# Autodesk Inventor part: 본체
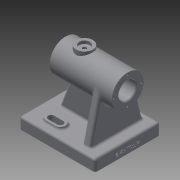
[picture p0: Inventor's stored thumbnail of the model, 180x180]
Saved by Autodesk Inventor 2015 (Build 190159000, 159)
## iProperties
Created: 2022-06
Part Number: 본체
Material: 일반
Document SubType Name: Modeling
Designer: 10401
Density: 1 g/cm^3
Appearance: 기본값
Author: 10401
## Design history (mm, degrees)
sketch "스케치1"
  geometry: C1 r 21 at (0, 0); 1 further point
  constraints: 1 centre point, 1 coincident
  dimensions: "d0" = 42 diameter of C1
extrude "돌출1" new body sketch "스케치1" stored distance "d1" = 82; taper "d2" = 0 deg
sketch "스케치2"
  geometry: L1 (41, 21)-(41, -21) reference; L2 (41, -21)-(-41, -21) reference; L3 (-41, -21)-(-41, 21) reference; L4 (-41, 21)-(41, 21) reference; L5 (41, 0)-(-41, 0); L6 (41, 14.5)-(-21, 14.5); L7 (-21, 14.5)-(-21, 11.5); L8 (-21, 11.5)-(-41, 11.5); 1 further point
  constraints: 8 end point, 2 horizontal, 2 midpoint, 2 point on line, 1 perpendicular
  dimensions: "d3" = 62 distance of L6.start L6.end; "d4" = 29 diameter of L6 L5; "d5" = 23 diameter of L8 L5
revolve "회전1" sketch "스케치2" stored, may be unused: angle "d6" = 90 deg
node "작업 평면2"
sketch "스케치4"
  geometry: L1 (-59, 43)-(41, 43); L2 (41, 43)-(41, -43); L3 (41, -43)-(-59, -43); L4 (-59, -43)-(-59, 43); L5 (41, -21)-(41, 21) reference; L6 (-59, 0)-(41, 0); 1 further point
  constraints: 10 end point, 2 midpoint, 2 parallel, 1 collinear, 1 horizontal, 1 perpendicular, 1 other
  dimensions: "d12" = 86 distance of L1.end L2.end; "d13" = 100 distance of L1.start L1.end
extrude "돌출2" join sketch "스케치4" distance "d14" = 15; taper "d15" = 0 deg
sketch "스케치5"
  geometry: L1 (41, 43)-(-59, 43) reference; L2 (-59, 43)-(-59, -43) reference; L3 (41, -43)-(41, 43) reference; L4 (-44, 5)-(26, 5); L5 (26, 5)-(26, -5); L6 (26, -5)-(-44, -5); L7 (-44, -5)-(-44, 5); L8 (16, 35)-(26, 35); L9 (26, 35)-(26, -35); L10 (26, -35)-(16, -35); L11 (16, -35)-(16, 35); L12 (16, 35)-(26, -35); L13 (26, 35)-(16, -35); L14 (-59, -43)-(41, -43) reference; 4 further points
  constraints: 20 end point, 4 parallel, 3 midpoint, 2 horizontal, 2 perpendicular, 1 collinear, 1 horizontal alignment
  dimensions: "d16" = 10 distance between parallel lines of L9 L11; "d17" = 10 distance of L6.end L4.start; "d18" = 15 distance between parallel lines of L3 L9; "d20" = 15 distance between parallel lines of L2 L7; "d139" = 5 distance from line of L6 point (0, 0); "d140" = 8 distance between parallel lines of L14 L10; "d141" = 8 distance between parallel lines of L1 L8
extrude "돌출3" join sketch "스케치5" distance "d21" = 57; taper "d22" = 0 deg
feature "면 기울기1" dims angle "d23" = 20 deg
node "작업 평면3"
sketch "스케치6"
  geometry: L1 (-15, 86)-(0, 86) reference; L2 (0, 86)-(0, 0) reference; L3 (0, 0)-(-15, 0) reference; L4 (-15, 0)-(-15, 38) reference; L5 (-15, 48)-(-15, 86) reference; L6 (-76.814, 22.559)-(-15, 8); L7 (-76.814, 63.441)-(-15, 78); L8 (-72, 48)-(-61.644, 48) reference; L9 (-61.644, 38)-(-72, 38) reference; L10 (-72, 38)-(-72, 48) reference; L11 (-15, 38)-(-15, 48) reference; L12 (-15, 38)-(-51.604, 38) reference; L13 (-51.604, 48)-(-15, 48) reference; A1 r 11.5 centre (-72, 43) between (-61.644, 48) and (-61.644, 38) reference; A2 r 21 centre (-72, 43) between (-51.604, 48) and (-51.604, 38) reference; A3 r 11.5 centre (-72, 43) between (-61.644, 38) and (-61.644, 48) reference; A4 r 21 centre (-72, 43) between (-51.604, 38) and (-51.604, 48) reference; 1 further point
  constraints: 4 end point, 2 point on circle, 2 point on line, 2 tangent
  dimensions: "d25" = 8 distance from line of L7.end L1; "d26" = 8 distance from line of L6.end L3
extrude "돌출4" join sketch "스케치6" distance "d27" = 10; taper "d28" = 0 deg
sketch "스케치7"
  geometry: C1 r 12.5 at (0, 0) reference
extrude "돌출5" cut sketch "스케치7" stored distance "d29" = 10; taper "d30" = 0 deg
sketch "스케치9"
  geometry: C1 r 15.5 at (0, 0) reference; C2 r 21 at (0, 0) reference; C3 r 11.5 at (0, 0)
  constraints: 1 centre point, 1 coincident
  dimensions: "d34" = 23 diameter of C3
extrude "돌출7" join sketch "스케치9" distance "d35" = 20; taper "d36" = 0 deg
sketch "스케치10"
  geometry: L1 (41, 43)-(-59, 43) reference; L2 (-59, 43)-(-59, -43) reference; L3 (-37, 27)-(-17, 27); L4 (-33, 23)-(-21, 23); L5 (-21, 31)-(-33, 31); L6 (-37, -27)-(-17, -27); L7 (-33, -31)-(-21, -31); L8 (-21, -23)-(-33, -23); L9 (-21, 33)-(-33, 33); L10 (-33, 21)-(-21, 21); L11 (-21, -33)-(-33, -33); L12 (-33, -21)-(-21, -21); A1 r 4 centre (-33, 27) between (-33, 31) and (-33, 23); A2 r 4 centre (-21, 27) between (-21, 23) and (-21, 31); A3 r 4 centre (-33, -27) between (-33, -23) and (-33, -31); A4 r 4 centre (-21, -27) between (-21, -31) and (-21, -23); A5 r 6 centre (-33, 27) between (-33, 33) and (-33, 21); A6 r 6 centre (-21, 27) between (-21, 21) and (-21, 33); A7 r 6 centre (-33, -27) between (-33, -21) and (-33, -33); A8 r 6 centre (-21, -27) between (-21, -33) and (-21, -21); 3 further points
  constraints: 24 end point, 20 point on circle, 8 centre point, 8 tangent, 6 parallel, 4 point on line, 2 midpoint, 1 horizontal, 6 other
  dimensions: "d37" = 12 distance of L5.start L5.end; "d38" = 26 distance from line of L2 A1.centre; "d40" = 16 distance from line of point (-27, 27) L1; "d41" = 26 distance from line of L2 A3.centre; "d43" = 8 distance between parallel lines of L4 L5; "d44" = 8 distance between parallel lines of L7 L8; "d47" = 54 distance of point (-27, -27) point (-27, 27); "d79" = 2 radial gap between concentric circles of A2 A6; "d80" = 2 distance between parallel lines of L7 L11
extrude "돌출8" cut sketch "스케치10" stored distance "d48" = 20; taper "d49" = 0 deg
sketch "스케치11"
  geometry: C1 r 11.5 at (0, 0) reference; 1 further point
  dimensions: "d50" = 18 distance of C1.centre point (-18, 0)
hole "구멍1" sketch "스케치11" at (-18, 0) diameter "d51" = 2.459; stored, may be unused: countersink angle "d55" = 90 deg, drill point angle "d57" = 118 deg; dims "d52" = 8, "d53" = 4, "d54" = 2, "d56" = 10
sketch "스케치13"
  geometry: C1 r 11.5 at (0, 0) reference; C2 r 14.5 at (0, 0) reference
extrude "돌출10" cut sketch "스케치13" stored distance "d60" = 20; taper "d61" = 0 deg
sketch "스케치14"
  geometry: C1 r 14.5 at (0, 0) reference; 1 further point
  constraints: 1 horizontal alignment
  dimensions: "d65" = 18 distance of C1.centre point (18, 0)
hole "구멍2" sketch "스케치14" at (18, 0) diameter "d66" = 2.459; stored, may be unused: countersink angle "d70" = 90 deg, drill point angle "d72" = 118 deg; dims "d67" = 8, "d68" = 4, "d69" = 2, "d71" = 10
chamfer "모따기2" distance "d76" = 1; stored, may be unused: second distance "d77" = 2, angle "d78" = 45 deg
sketch "스케치16"
  geometry: L1 (-21, 23)-(-33, 23) reference; L2 (-33, 31)-(-21, 31) reference; L3 (-21, -31)-(-33, -31) reference; L4 (-33, -23)-(-21, -23) reference; L5 (-21, 20)-(-33, 20); L6 (-33, 34)-(-21, 34); L7 (-21, -34)-(-33, -34); L8 (-33, -20)-(-21, -20); A1 r 4 centre (-21, 27) between (-21, 23) and (-21, 31) reference; A2 r 4 centre (-33, 27) between (-33, 31) and (-33, 23) reference; A3 r 4 centre (-21, -27) between (-21, -31) and (-21, -23) reference; A4 r 4 centre (-33, -27) between (-33, -23) and (-33, -31) reference; A5 r 7 centre (-21, 27) between (-21, 20) and (-21, 34); A6 r 7 centre (-33, 27) between (-33, 34) and (-33, 20); A7 r 7 centre (-21, -27) between (-21, -34) and (-21, -20); A8 r 7 centre (-33, -27) between (-33, -20) and (-33, -34); 1 further point
  constraints: 8 end point, 8 point on circle, 4 centre point, 6 other
  dimensions: "d81" = 3 radial gap between concentric circles of A1 A5; "d82" = 3 radial gap between concentric circles of A3 A7
node "작업 평면4"
sketch "스케치17"
  geometry: L1 (41, -21)-(41, 21) reference; L2 (-41, 21)-(-41, -21) reference; C1 r 11 at (-16, 0); 1 further point
  constraints: 1 centre point, 1 horizontal alignment
  dimensions: "d114" = 22 diameter of C1; "d126" = 25 distance from line of L2 C1.centre
extrude "돌출12" join sketch "스케치17" stored distance "d87" = 3; taper "d88" = 0 deg
fillet "모깎기3" dims "d101" = 3
fillet "모깎기4" dims "d102" = 3
fillet "모깎기5" dims "d103" = 3
fillet "모깎기6" dims "d104" = 3
extrude "돌출14" join sketch "스케치16" distance "d105" = 3; taper "d106" = 0 deg
fillet "모깎기7" dims "d107" = 3
fillet "모깎기8" dims "d108" = 3
sketch "스케치20"
  geometry: L1 (0, 80)-(0, 0) reference; 2 further points
  constraints: 1 horizontal alignment, 1 other
  dimensions: "d109" = 6 distance from line of L1 point (-6, 40)
feature "엠보싱2" sketch "스케치20" dims "d112" = 0.5, "d113" = 0
sketch "스케치22"
  geometry: C1 r 11 at (0, 0) reference; C2 r 7 at (0, 0); 1 further point
  constraints: 1 centre point, 1 coincident
  dimensions: "d127" = 14 diameter of C2
extrude "돌출16" cut sketch "스케치22" distance "d128" = 4; taper "d129" = 0 deg
sketch "스케치23"
  geometry: C1 r 7 at (0, 0) reference; 1 further point
hole "구멍5" sketch "스케치23" at (0, 0) diameter "d130" = 4.917; stored, may be unused: countersink angle "d134" = 90 deg, drill point angle "d136" = 0 deg; dims "d131" = 12, "d132" = 4, "d133" = 2, "d135" = 24
node "솔리드1"
pattern_circular "원형 패턴1" dims angle "d63" = 360 deg
pattern_circular "원형 패턴2" dims angle "d74" = 360 deg
node "절단 모서리 투영1"
node "절단 모서리 투영2"
other parameters: "d11" = -72, "d24" = -15, "d85" = 24
